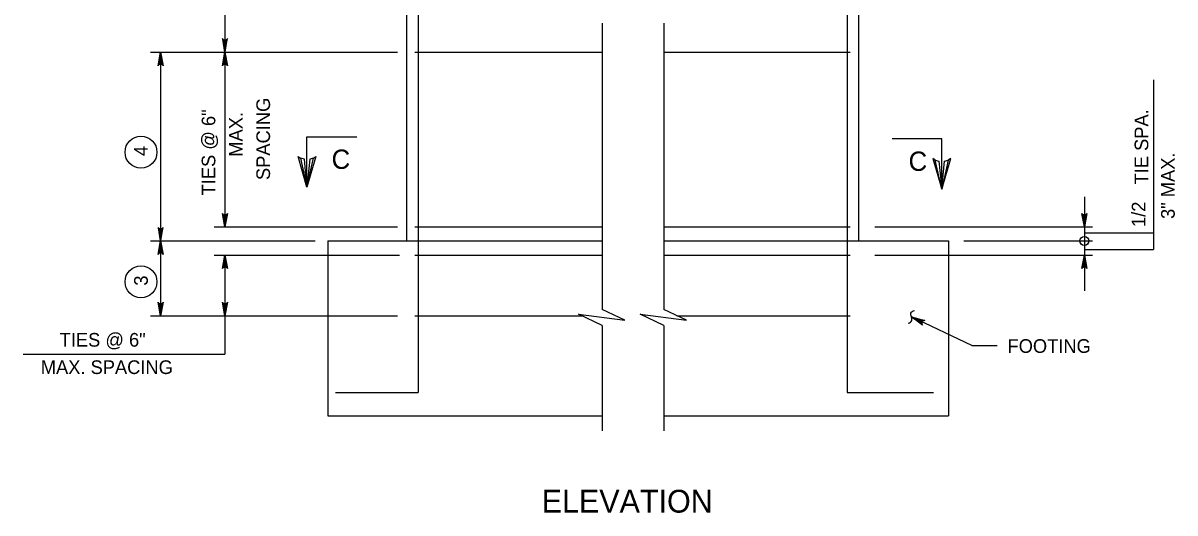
# Model space of a CAD drawing. Extents: x 646165 to 651486, y 296916 to 299292.
# Drawn here: x 649233.6 to 649486.4, y 297204.7 to 297312.1 of the extents above; entities that cross this region are included whole.
import ezdxf

# ---------------------------------------------------------------- set-up
doc = ezdxf.new("R2010")
doc.units = 0
for name, color, linetype in [('1', 7, 'Continuous'), ('51', 7, 'Continuous'), ('52', 7, 'Continuous'), ('53', 7, 'Continuous'), ('54', 7, 'Continuous')]:
    doc.layers.add(name, color=color, linetype=linetype)

msp = doc.modelspace()

# ---------------------------------------------------------------- linework, layer by layer
at = {"layer": '1'}
for p, q in [((649295.94, 297287.17), (649306.86, 297287.17)), ((649295.94, 297276.1), (649295.94, 297287.17)), ((649435.26, 297286.73), (649424.33, 297286.73)), ((649435.26, 297275.66), (649435.26, 297286.73))]:
    msp.add_line(p, q, dxfattribs=at)
for points in [[(649297.41, 297282.52), (649296.56, 297282.28), (649295.94, 297276.1), (649297.41, 297282.52), (649297.92, 297282.85), (649295.94, 297276.1), (649295.38, 297282.28), (649294.54, 297282.5), (649295.94, 297276.1), (649293.99, 297282.85), (649294.54, 297282.5)], [(649433.79, 297282.08), (649434.63, 297281.84), (649435.26, 297275.66), (649433.79, 297282.08), (649433.27, 297282.41), (649435.26, 297275.66), (649435.82, 297281.83), (649436.65, 297282.06), (649435.26, 297275.66), (649437.21, 297282.41), (649436.65, 297282.06)]]:
    msp.add_lwpolyline(points, dxfattribs=at)
at = {"layer": '51'}
for p, q in [((649416.99, 297476.15), (649416.99, 297264.33)), ((649317.81, 297435.49), (649317.81, 297264.33)), ((649300.54, 297264.33), (649360.73, 297264.33)), ((649300.54, 297264.33), (649300.54, 297226)), ((649374.25, 297264.33), (649436.75, 297264.33)), ((649436.75, 297264.33), (649436.75, 297226)), ((649300.54, 297226), (649360.73, 297226)), ((649374.25, 297226), (649436.75, 297226))]:
    msp.add_line(p, q, dxfattribs=at)
at = {"layer": '52'}
for p, q in [((649277.94, 297470.15), (649277.94, 297267.41)), ((649360.73, 297312.13), (649360.73, 297249.27)), ((649374.25, 297312.13), (649374.25, 297249.29)), ((649261.61, 297305.74), (649315.81, 297305.74)), ((649263.84, 297305.74), (649263.84, 297247.92)), ((649481.71, 297299.69), (649481.71, 297262.46)), ((649466.54, 297274.01), (649466.54, 297253.39)), ((649275.6, 297267.41), (649315.81, 297267.41)), ((649420.59, 297267.41), (649468.32, 297267.41)), ((649261.61, 297264.33), (649297.73, 297264.33)), ((649440.07, 297264.33), (649468.32, 297264.33)), ((649466.67, 297266.13), (649481.71, 297266.13)), ((649466.67, 297262.46), (649481.71, 297262.46)), ((649275.6, 297261.25), (649316.22, 297261.25)), ((649277.94, 297261.25), (649277.94, 297239.47)), ((649420.59, 297261.25), (649468.32, 297261.25)), ((649261.61, 297247.92), (649315.81, 297247.92)), ((649441.83, 297241.37), (649428.58, 297247.69)), ((649360.73, 297245.77), (649360.73, 297222.72)), ((649374.25, 297245.77), (649374.25, 297222.72)), ((649441.83, 297241.37), (649447.42, 297241.37)), ((649233.64, 297239.47), (649277.94, 297239.47))]:
    msp.add_line(p, q, dxfattribs=at)
for points in [[(649277.94, 297305.74), (649278.5, 297308.73), (649278.42, 297308.61), (649278.34, 297308.5), (649278.24, 297308.44), (649278.14, 297308.38), (649278.04, 297308.36), (649277.94, 297308.34), (649277.84, 297308.36), (649277.74, 297308.38), (649277.64, 297308.44), (649277.54, 297308.5), (649277.46, 297308.61), (649277.38, 297308.73), (649277.94, 297305.74), (649277.46, 297308.61), (649277.54, 297308.5), (649277.94, 297305.74), (649277.64, 297308.44), (649277.74, 297308.38), (649277.94, 297305.74), (649277.84, 297308.36), (649277.94, 297308.34), (649277.94, 297305.74), (649278.04, 297308.36), (649278.14, 297308.38), (649277.94, 297305.74), (649278.24, 297308.44), (649278.34, 297308.5), (649277.94, 297305.74), (649278.42, 297308.61)], [(649263.84, 297305.74), (649264.4, 297302.76), (649264.32, 297302.88), (649264.24, 297302.99), (649264.14, 297303.05), (649264.04, 297303.11), (649263.94, 297303.13), (649263.84, 297303.14), (649263.74, 297303.13), (649263.64, 297303.11), (649263.54, 297303.05), (649263.44, 297302.99), (649263.36, 297302.88), (649263.28, 297302.76), (649263.84, 297305.74), (649263.36, 297302.88), (649263.44, 297302.99), (649263.84, 297305.74), (649263.54, 297303.05), (649263.64, 297303.11), (649263.84, 297305.74), (649263.74, 297303.13), (649263.84, 297303.14), (649263.84, 297305.74), (649263.94, 297303.13), (649264.04, 297303.11), (649263.84, 297305.74), (649264.14, 297303.05), (649264.24, 297302.99), (649263.84, 297305.74), (649264.32, 297302.88)], [(649263.84, 297305.74), (649264.4, 297302.76), (649264.32, 297302.88), (649264.24, 297302.99), (649264.14, 297303.05), (649264.04, 297303.11), (649263.94, 297303.13), (649263.84, 297303.14), (649263.74, 297303.13), (649263.64, 297303.11), (649263.54, 297303.05), (649263.44, 297302.99), (649263.36, 297302.88), (649263.28, 297302.76), (649263.84, 297305.74), (649263.36, 297302.88), (649263.44, 297302.99), (649263.84, 297305.74), (649263.54, 297303.05), (649263.64, 297303.11), (649263.84, 297305.74), (649263.74, 297303.13), (649263.84, 297303.14), (649263.84, 297305.74), (649263.94, 297303.13), (649264.04, 297303.11), (649263.84, 297305.74), (649264.14, 297303.05), (649264.24, 297302.99), (649263.84, 297305.74), (649264.32, 297302.88)], [(649277.94, 297305.74), (649278.5, 297302.76), (649278.42, 297302.88), (649278.34, 297302.99), (649278.24, 297303.05), (649278.14, 297303.11), (649278.04, 297303.13), (649277.94, 297303.14), (649277.84, 297303.13), (649277.74, 297303.11), (649277.64, 297303.05), (649277.54, 297302.99), (649277.46, 297302.88), (649277.38, 297302.76), (649277.94, 297305.74), (649277.46, 297302.88), (649277.54, 297302.99), (649277.94, 297305.74), (649277.64, 297303.05), (649277.74, 297303.11), (649277.94, 297305.74), (649277.84, 297303.13), (649277.94, 297303.14), (649277.94, 297305.74), (649278.04, 297303.13), (649278.14, 297303.11), (649277.94, 297305.74), (649278.24, 297303.05), (649278.34, 297302.99), (649277.94, 297305.74), (649278.42, 297302.88)], [(649277.94, 297267.41), (649277.38, 297270.39), (649277.46, 297270.28), (649277.54, 297270.16), (649277.64, 297270.1), (649277.74, 297270.04), (649277.84, 297270.03), (649277.94, 297270.01), (649278.04, 297270.03), (649278.14, 297270.04), (649278.24, 297270.1), (649278.34, 297270.16), (649278.42, 297270.28), (649278.5, 297270.39), (649277.94, 297267.41), (649278.42, 297270.28), (649278.34, 297270.16), (649277.94, 297267.41), (649278.24, 297270.1), (649278.14, 297270.04), (649277.94, 297267.41), (649278.04, 297270.03), (649277.94, 297270.01), (649277.94, 297267.41), (649277.84, 297270.03), (649277.74, 297270.04), (649277.94, 297267.41), (649277.64, 297270.1), (649277.54, 297270.16), (649277.94, 297267.41), (649277.46, 297270.28)], [(649466.54, 297267.41), (649465.98, 297270.39), (649466.06, 297270.28), (649466.14, 297270.16), (649466.24, 297270.1), (649466.34, 297270.04), (649466.44, 297270.03), (649466.54, 297270.01), (649466.64, 297270.03), (649466.74, 297270.04), (649466.84, 297270.1), (649466.94, 297270.16), (649467.02, 297270.28), (649467.1, 297270.39), (649466.54, 297267.41), (649467.02, 297270.28), (649466.94, 297270.16), (649466.54, 297267.41), (649466.84, 297270.1), (649466.74, 297270.04), (649466.54, 297267.41), (649466.64, 297270.03), (649466.54, 297270.01), (649466.54, 297267.41), (649466.44, 297270.03), (649466.34, 297270.04), (649466.54, 297267.41), (649466.24, 297270.1), (649466.14, 297270.16), (649466.54, 297267.41), (649466.06, 297270.28)], [(649263.84, 297264.33), (649264.4, 297267.32), (649264.32, 297267.2), (649264.24, 297267.09), (649264.14, 297267.03), (649264.04, 297266.97), (649263.94, 297266.95), (649263.84, 297266.93), (649263.74, 297266.95), (649263.64, 297266.97), (649263.54, 297267.03), (649263.44, 297267.09), (649263.36, 297267.2), (649263.28, 297267.32), (649263.84, 297264.33), (649263.36, 297267.2), (649263.44, 297267.09), (649263.84, 297264.33), (649263.54, 297267.03), (649263.64, 297266.97), (649263.84, 297264.33), (649263.74, 297266.95), (649263.84, 297266.93), (649263.84, 297264.33), (649263.94, 297266.95), (649264.04, 297266.97), (649263.84, 297264.33), (649264.14, 297267.03), (649264.24, 297267.09), (649263.84, 297264.33), (649264.32, 297267.2)], [(649263.84, 297264.33), (649264.4, 297261.35), (649264.32, 297261.47), (649264.24, 297261.58), (649264.14, 297261.64), (649264.04, 297261.7), (649263.94, 297261.72), (649263.84, 297261.73), (649263.74, 297261.72), (649263.64, 297261.7), (649263.54, 297261.64), (649263.44, 297261.58), (649263.36, 297261.47), (649263.28, 297261.35), (649263.84, 297264.33), (649263.36, 297261.47), (649263.44, 297261.58), (649263.84, 297264.33), (649263.54, 297261.64), (649263.64, 297261.7), (649263.84, 297264.33), (649263.74, 297261.72), (649263.84, 297261.73), (649263.84, 297264.33), (649263.94, 297261.72), (649264.04, 297261.7), (649263.84, 297264.33), (649264.14, 297261.64), (649264.24, 297261.58), (649263.84, 297264.33), (649264.32, 297261.47)], [(649277.94, 297261.25), (649278.5, 297258.27), (649278.42, 297258.38), (649278.34, 297258.5), (649278.24, 297258.56), (649278.14, 297258.62), (649278.04, 297258.63), (649277.94, 297258.65), (649277.84, 297258.63), (649277.74, 297258.62), (649277.64, 297258.56), (649277.54, 297258.5), (649277.46, 297258.38), (649277.38, 297258.27), (649277.94, 297261.25), (649277.46, 297258.38), (649277.54, 297258.5), (649277.94, 297261.25), (649277.64, 297258.56), (649277.74, 297258.62), (649277.94, 297261.25), (649277.84, 297258.63), (649277.94, 297258.65), (649277.94, 297261.25), (649278.04, 297258.63), (649278.14, 297258.62), (649277.94, 297261.25), (649278.24, 297258.56), (649278.34, 297258.5), (649277.94, 297261.25), (649278.42, 297258.38)], [(649466.54, 297261.25), (649467.1, 297258.27), (649467.02, 297258.38), (649466.94, 297258.5), (649466.84, 297258.56), (649466.74, 297258.62), (649466.64, 297258.63), (649466.54, 297258.65), (649466.44, 297258.63), (649466.34, 297258.62), (649466.24, 297258.56), (649466.14, 297258.5), (649466.06, 297258.38), (649465.98, 297258.27), (649466.54, 297261.25), (649466.06, 297258.38), (649466.14, 297258.5), (649466.54, 297261.25), (649466.24, 297258.56), (649466.34, 297258.62), (649466.54, 297261.25), (649466.44, 297258.63), (649466.54, 297258.65), (649466.54, 297261.25), (649466.64, 297258.63), (649466.74, 297258.62), (649466.54, 297261.25), (649466.84, 297258.56), (649466.94, 297258.5), (649466.54, 297261.25), (649467.02, 297258.38)], [(649263.84, 297247.92), (649263.28, 297250.9), (649263.36, 297250.79), (649263.44, 297250.67), (649263.54, 297250.61), (649263.64, 297250.55), (649263.74, 297250.53), (649263.84, 297250.52), (649263.94, 297250.53), (649264.04, 297250.55), (649264.14, 297250.61), (649264.24, 297250.67), (649264.32, 297250.79), (649264.4, 297250.9), (649263.84, 297247.92), (649264.32, 297250.79), (649264.24, 297250.67), (649263.84, 297247.92), (649264.14, 297250.61), (649264.04, 297250.55), (649263.84, 297247.92), (649263.94, 297250.53), (649263.84, 297250.52), (649263.84, 297247.92), (649263.74, 297250.53), (649263.64, 297250.55), (649263.84, 297247.92), (649263.54, 297250.61), (649263.44, 297250.67), (649263.84, 297247.92), (649263.36, 297250.79)], [(649277.94, 297247.92), (649277.38, 297250.9), (649277.46, 297250.79), (649277.54, 297250.67), (649277.64, 297250.61), (649277.74, 297250.55), (649277.84, 297250.53), (649277.94, 297250.52), (649278.04, 297250.53), (649278.14, 297250.55), (649278.24, 297250.61), (649278.34, 297250.67), (649278.42, 297250.79), (649278.5, 297250.9), (649277.94, 297247.92), (649278.42, 297250.79), (649278.34, 297250.67), (649277.94, 297247.92), (649278.24, 297250.61), (649278.14, 297250.55), (649277.94, 297247.92), (649278.04, 297250.53), (649277.94, 297250.52), (649277.94, 297247.92), (649277.84, 297250.53), (649277.74, 297250.55), (649277.94, 297247.92), (649277.64, 297250.61), (649277.54, 297250.67), (649277.94, 297247.92), (649277.46, 297250.79)], [(649360.73, 297245.77), (649355.55, 297248.31), (649365.69, 297246.93), (649360.73, 297249.29)], [(649374.25, 297245.77), (649369.07, 297248.31), (649379.21, 297246.93), (649374.25, 297249.29)], [(649428.58, 297247.69), (649431.51, 297246.91), (649431.23, 297246.86), (649431.04, 297246.73), (649430.92, 297246.57), (649430.87, 297246.37), (649430.89, 297246.14), (649431.03, 297245.9), (649428.58, 297247.69), (649430.89, 297246.14), (649430.87, 297246.37), (649428.58, 297247.69), (649430.92, 297246.57), (649431.04, 297246.73), (649428.58, 297247.69), (649431.23, 297246.86)]]:
    msp.add_lwpolyline(points, dxfattribs=at)
for centre in [(649259.52, 297283.8), (649259.52, 297255.38)]:
    msp.add_circle(centre, 3.5, dxfattribs=at)
msp.add_spline([(649427.88, 297246.29), (649428.67, 297246.87), (649428.49, 297248.51), (649429.23, 297249.1)], degree=3, dxfattribs=at)
at = {"layer": '54'}
for p, q in [((649320.31, 297383.24), (649320.31, 297231.11)), ((649414.49, 297349.91), (649414.49, 297231.11)), ((649319.64, 297305.74), (649360.73, 297305.74)), ((649374.25, 297305.74), (649415.15, 297305.74)), ((649319.64, 297267.41), (649360.73, 297267.41)), ((649374.25, 297267.41), (649415.15, 297267.41)), ((649319.64, 297261.25), (649360.73, 297261.25)), ((649374.25, 297261.25), (649415.15, 297261.25)), ((649319.64, 297247.92), (649356.35, 297247.92)), ((649377.14, 297247.92), (649415.15, 297247.92)), ((649302.21, 297231.11), (649320.31, 297231.11)), ((649414.49, 297231.11), (649433.42, 297231.11))]:
    msp.add_line(p, q, dxfattribs=at)
msp.add_circle((649466.54, 297264.35), 0.986, dxfattribs=at)

# ---------------------------------------------------------------- texts
at = {"layer": '1'}
for p in [(649301.35, 297280.15), (649427.96, 297279.71)]:
    msp.add_text('C', height=4.23, dxfattribs=at).set_placement(p)
at = {"layer": '53'}
for s, p in [('SPACING', (649287.84, 297277.69)), ('TIES @ 6"', (649275.84, 297274.32)), ('MAX.', (649281.84, 297282.81)), ('TIE SPA.', (649480.56, 297276.72)), ('4', (649261.02, 297282.95)), ('  3" MAX.', (649486.37, 297266.93)), ('1/2', (649479.93, 297267.39)), ('3', (649261.02, 297254.53))]:
    msp.add_text(s, height=3, rotation=90, dxfattribs=at).set_placement(p)
for s, height, p in [('TIES @ 6"', 3, (649241.68, 297241.15)), ('FOOTING', 3, (649449.67, 297239.79)), ('MAX. SPACING', 3, (649237.54, 297235.15)), ('ELEVATION', 5, (649347.45, 297204.75))]:
    msp.add_text(s, height=height, dxfattribs=at).set_placement(p)

doc.saveas('drawing.dxf')
